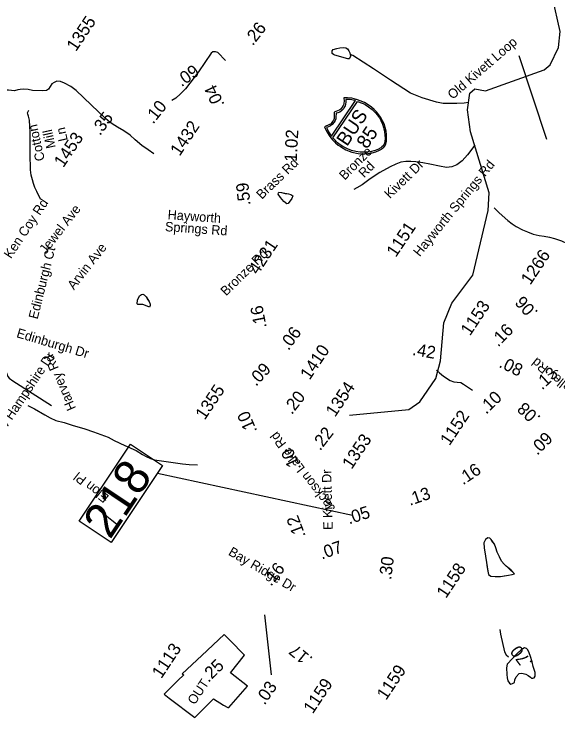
# Model space of a CAD drawing. Extents: x 1716282 to 1717158, y 799307 to 801078.
# Drawn here: x 1716897.5 to 1716976.7, y 800924.3 to 801026.4 of the extents above; entities that cross this region are included whole.
import ezdxf

# ---------------------------------------------------------------- set-up
doc = ezdxf.new("R2010")
doc.units = 0
for name, color, linetype in [('Exist Boundary Political City Limit New Hole', 7, 'Continuous'), ('Exist Hydrographic Misc Water Feature', 7, 'Continuous'), ('Exist Hydrographic Pond Under 1500 Sq Ft', 7, 'Continuous'), ('Exist Road Non-System Type 51', 7, 'Continuous'), ('Exist Road Non-System Type 51 Label', 7, 'Continuous'), ('Exist Road Primary Interstate Mileage Hundredths English Label', 7, 'Continuous'), ('Exist Road Primary Interstate Shield CELL', 7, 'Continuous'), ('Exist Road Primary Interstate Shield Number Label', 7, 'Continuous'), ('Exist Road Secondary Mileage Hundredths English Label', 7, 'Continuous'), ('Exist Road Secondary Mileage Tenths English Label', 7, 'Continuous'), ('Exist Road Secondary Structure Standard Bridge Number Label', 7, 'Continuous'), ('Exist Road Secondary Type 51 Label', 7, 'Continuous'), ('Exist Road Secondary Type 51 Number Label', 7, 'Continuous')]:
    doc.layers.add(name, color=color, linetype=linetype)

msp = doc.modelspace()

# ---------------------------------------------------------------- linework, layer by layer
at = {"layer": 'Exist Boundary Political City Limit New Hole'}
msp.add_lwpolyline([(1716926.55, 800926.63), (1716927.99, 800925.74), (1716928.64, 800925.36), (1716928.77, 800925.4), (1716931.48, 800928.47), (1716929, 800930.44), (1716931.03, 800932.98), (1716928.93, 800935.19), (1716928.1, 800935.99), (1716924.84, 800932.96), (1716921.98, 800930.29), (1716922.19, 800930.12), (1716921.36, 800929.31), (1716919.35, 800927.34), (1716920.08, 800926.73), (1716923.81, 800923.9), (1716926.55, 800926.63)], dxfattribs=at)
at = {"layer": 'Exist Hydrographic Misc Water Feature'}
for points in [[(1716946.34, 800967.98), (1716954.98, 800968.81), (1716956.62, 800969.9), (1716958.93, 800973.29), (1716959.64, 800975.89), (1716960.09, 800981.43), (1716961.27, 800984.28), (1716964.34, 800988.34), (1716966.58, 800997.77), (1716966.69, 801000.34), (1716963.97, 801009.23), (1716963.54, 801012.44), (1716963.89, 801014.85), (1716964.64, 801015.5), (1716966.16, 801015.19), (1716974.71, 801018.28), (1716975.61, 801018.99), (1716976.81, 801021.53), (1716977.04, 801023.86), (1716975.95, 801028.85), (1716977.09, 801034.23), (1716978.2, 801037.01)], [(1716963.69, 801013.49), (1716963.08, 801013.43), (1716961.99, 801013.37), (1716960.95, 801013.34), (1716960.01, 801013.35), (1716959.03, 801013.56), (1716956.97, 801014.2), (1716956.2, 801014.47), (1716955.24, 801014.85), (1716952.35, 801016.75), (1716949.85, 801018.39), (1716946.86, 801020.33), (1716946.45, 801020.5)], [(1716917.84, 801006.04), (1716917.01, 801006.61), (1716916.11, 801007.25), (1716915.12, 801008.07), (1716914.39, 801008.75), (1716913.48, 801009.37), (1716912.55, 801009.9), (1716912.14, 801010.14), (1716911.5, 801010.58), (1716910.78, 801011.18), (1716908.72, 801013.15), (1716906.53, 801015.24), (1716905.72, 801015.86), (1716904.84, 801016.32), (1716904.22, 801016.54), (1716903.71, 801016.61), (1716903.3, 801016.43), (1716902.99, 801016.22), (1716902.5, 801015.46), (1716902.19, 801015.26), (1716901.65, 801015.2), (1716900.16, 801015.27), (1716899.52, 801015.42), (1716898.79, 801015.43), (1716898.34, 801015.39), (1716898.03, 801015.35), (1716897.52, 801015.21)], [(1716897.52, 801015.21), (1716896.64, 801015.32), (1716895.85, 801015.3), (1716894.14, 801014.75), (1716893.02, 801014.28), (1716892.11, 801013.88), (1716891.63, 801013.65)], [(1716964.63, 801007.31), (1716963.56, 801005.9), (1716962.78, 801005.02), (1716962, 801004.44), (1716961.29, 801004.11), (1716960.5, 801004.05), (1716959.45, 801004.21), (1716958.04, 801004.51), (1716957.06, 801004.72), (1716956.01, 801004.87), (1716955.29, 801004.91), (1716954.58, 801004.9), (1716953.83, 801004.82), (1716953.13, 801004.52), (1716952.29, 801004.11), (1716950.77, 801003.32), (1716949.8, 801002.68), (1716949.18, 801002.23), (1716948.19, 801001.5), (1716947.44, 801001.07), (1716946.98, 801000.82)], [(1716938.09, 800999.93), (1716937.96, 800999.53), (1716937.65, 800999.14), (1716937.43, 800998.81), (1716937.23, 800998.73), (1716936.78, 800999.1), (1716936.28, 800999.66), (1716935.96, 801000.16), (1716936.01, 801000.34), (1716936.08, 801000.43), (1716936.46, 801000.38), (1716936.99, 801000.23), (1716937.46, 801000.19), (1716937.83, 801000.11), (1716938.09, 800999.93)], [(1716938.09, 800999.93), (1716937.96, 800999.53), (1716937.43, 800998.81), (1716937.23, 800998.73), (1716936.78, 800999.1), (1716936.28, 800999.66), (1716935.96, 801000.16), (1716936.01, 801000.34), (1716936.08, 801000.43), (1716936.46, 801000.38), (1716937.46, 801000.19), (1716937.83, 801000.11), (1716938.09, 800999.93)], [(1716967.46, 800998.14), (1716968.18, 800997.44), (1716969.41, 800996.31), (1716970.04, 800995.85), (1716970.64, 800995.44), (1716971.58, 800994.97), (1716972.31, 800994.65), (1716973.11, 800994.32), (1716974, 800994.13), (1716974.74, 800994.04), (1716975.48, 800993.89), (1716976.25, 800993.68), (1716977.27, 800993.37), (1716978.1, 800992.98), (1716978.92, 800992.49), (1716980.01, 800991.78), (1716980.67, 800991.3), (1716981.58, 800990.53), (1716984, 800988.11), (1716984.85, 800987.24)], [(1716917.2, 800983.71), (1716916.64, 800983.92), (1716916.22, 800984.07), (1716915.76, 800984.06), (1716915.53, 800984.08), (1716915.42, 800984.19), (1716915.45, 800984.69), (1716915.73, 800985.35), (1716916.03, 800985.53), (1716916.23, 800985.57), (1716916.45, 800985.49), (1716916.7, 800985.18), (1716916.98, 800984.77), (1716917.18, 800984.5), (1716917.29, 800984.14), (1716917.29, 800983.94), (1716917.2, 800983.71)], [(1716917.2, 800983.71), (1716916.64, 800983.92), (1716916.22, 800984.07), (1716915.76, 800984.06), (1716915.53, 800984.08), (1716915.42, 800984.19), (1716915.45, 800984.69), (1716915.73, 800985.35), (1716916.03, 800985.53), (1716916.23, 800985.57), (1716916.45, 800985.49), (1716916.7, 800985.18), (1716917.18, 800984.5), (1716917.29, 800984.14), (1716917.29, 800983.94), (1716917.2, 800983.71)], [(1716959.03, 800974.53), (1716959.48, 800974.12), (1716960.05, 800973.66), (1716961.02, 800973.03), (1716961.58, 800972.82), (1716962.05, 800972.78), (1716962.56, 800972.71), (1716962.98, 800972.5), (1716963.27, 800972.26), (1716964.27, 800971.62)], [(1716899.47, 800969.37), (1716900.44, 800968.89), (1716901.94, 800968), (1716902.71, 800967.58), (1716903.57, 800967.2), (1716904.79, 800966.87), (1716905.96, 800966.52), (1716907.77, 800965.99), (1716909.07, 800965.52), (1716911.17, 800964.75), (1716912.08, 800964.27), (1716913.59, 800963.56), (1716915.28, 800962.79), (1716916.21, 800962.25), (1716916.73, 800961.94), (1716917.33, 800961.63), (1716917.93, 800961.47), (1716922.03, 800960.89), (1716923.01, 800960.78), (1716924.18, 800960.75)], [(1716970.42, 800944.87), (1716969.91, 800945.36), (1716969.36, 800945.84), (1716968.88, 800946.27), (1716968.53, 800946.68), (1716968.2, 800947.33), (1716967.89, 800948), (1716967.68, 800948.63), (1716967.48, 800949.15), (1716967.12, 800949.65), (1716966.99, 800949.84), (1716966.83, 800950.05), (1716966.51, 800950.1), (1716966.2, 800949.85), (1716965.94, 800949.37), (1716965.99, 800948.63), (1716966.18, 800947.41), (1716966.31, 800946.51), (1716966.43, 800945.77), (1716966.5, 800945.26), (1716966.58, 800944.96), (1716966.62, 800944.76), (1716966.94, 800944.5), (1716967.59, 800944.44), (1716968.38, 800944.46), (1716968.91, 800944.56), (1716969.54, 800944.66), (1716970.04, 800944.77), (1716970.42, 800944.87)], [(1716970.42, 800944.87), (1716968.88, 800946.27), (1716968.53, 800946.68), (1716968.2, 800947.33), (1716967.89, 800948), (1716967.68, 800948.63), (1716967.48, 800949.15), (1716966.99, 800949.84), (1716966.83, 800950.05), (1716966.51, 800950.1), (1716966.2, 800949.85), (1716965.94, 800949.37), (1716965.99, 800948.63), (1716966.31, 800946.51), (1716966.5, 800945.26), (1716966.62, 800944.76), (1716966.94, 800944.5), (1716967.59, 800944.44), (1716968.38, 800944.46), (1716969.54, 800944.66), (1716970.04, 800944.77), (1716970.42, 800944.87)], [(1716968.25, 800936.76), (1716968.38, 800936.07), (1716968.94, 800933.51), (1716969.17, 800933.07), (1716969.51, 800932.74)]]:
    msp.add_lwpolyline(points, dxfattribs=at)
at = {"layer": 'Exist Hydrographic Pond Under 1500 Sq Ft'}
for points in [[(1716946.45, 801020.5), (1716946.49, 801020.26), (1716946.37, 801019.92), (1716946.31, 801019.89), (1716946.13, 801019.88), (1716944.21, 801020.42), (1716944.01, 801020.48), (1716943.81, 801020.65), (1716943.81, 801020.8), (1716943.82, 801021.03), (1716943.98, 801021.21), (1716944.51, 801021.37), (1716944.96, 801021.45), (1716945.45, 801021.5), (1716945.81, 801021.47), (1716946.05, 801021.3), (1716946.27, 801021.01), (1716946.4, 801020.74), (1716946.45, 801020.5)], [(1716970.13, 800932.54), (1716969.33, 800931.7), (1716969.24, 800931.14), (1716969.27, 800930.2), (1716969.35, 800929.68), (1716969.41, 800929.24), (1716969.66, 800928.93), (1716969.86, 800928.78), (1716970.13, 800928.86), (1716970.39, 800929.01), (1716970.44, 800929.41), (1716970.63, 800929.86), (1716971.07, 800930.32), (1716971.45, 800930.36), (1716972.03, 800930.21), (1716972.4, 800930.03), (1716972.72, 800929.78), (1716972.87, 800929.65), (1716973.07, 800929.63), (1716973.27, 800929.71), (1716973.39, 800929.93), (1716973.41, 800930.49), (1716973.14, 800931.34), (1716972.97, 800932.05), (1716972.75, 800932.82), (1716972.55, 800933.36), (1716972.35, 800933.79), (1716972.13, 800933.99), (1716971.85, 800934.07), (1716971.36, 800933.78), (1716970.8, 800933.26), (1716970.13, 800932.54)]]:
    msp.add_lwpolyline(points, dxfattribs=at)
at = {"layer": 'Exist Road Non-System Type 51'}
for p, q in [((1716971.02, 801020.36), (1716975.09, 801008.18)), ((1716909.82, 800954.18), (1716910, 800954.03)), ((1716910, 800954.03), (1716911.7, 800952.67)), ((1716911.7, 800952.67), (1716912.39, 800952.12))]:
    msp.add_line(p, q, dxfattribs=at)
for points in [[(1716928.28, 801019.64), (1716927.16, 801020.77), (1716926.82, 801020.9), (1716926.42, 801020.88), (1716926.2, 801020.69), (1716924.33, 801017.97), (1716922.46, 801015.48), (1716921.74, 801014.76), (1716921.03, 801014.13), (1716920.44, 801013.81)], [(1716901.39, 800999.37), (1716901.13, 800999.81), (1716900.78, 801000.52), (1716900.5, 801001.13), (1716900.3, 801001.69), (1716900.16, 801002.23), (1716899.97, 801002.94), (1716899.88, 801003.68), (1716899.85, 801004.46), (1716899.82, 801005.24), (1716899.8, 801006.02), (1716899.82, 801006.87), (1716899.83, 801007.73), (1716899.83, 801008.5), (1716899.81, 801009.22), (1716899.78, 801010.01), (1716899.71, 801010.91), (1716899.58, 801011.51), (1716899.46, 801011.82), (1716899.44, 801012.02), (1716899.6, 801012.38)], [(1716895.93, 800975.26), (1716896.58, 800973.57), (1716896.77, 800973.35), (1716897.31, 800972.94), (1716902.94, 800969.36)], [(1716912.39, 800952.12), (1716912.46, 800952.07)]]:
    msp.add_lwpolyline(points, dxfattribs=at)
at = {"layer": 'Exist Road Primary Interstate Shield CELL'}
for points in [[(1716951.5, 801007.16), (1716951.56, 801007.28), (1716951.64, 801007.45), (1716951.69, 801007.64), (1716951.73, 801007.86), (1716951.75, 801008.2), (1716951.77, 801008.48), (1716951.77, 801008.82), (1716951.7, 801009.33), (1716951.57, 801009.86), (1716951.39, 801010.39), (1716951.18, 801010.84), (1716950.91, 801011.3), (1716950.65, 801011.71), (1716950.31, 801012.13), (1716949.95, 801012.49), (1716949.55, 801012.82), (1716949.1, 801013.17), (1716948.54, 801013.5), (1716947.93, 801013.77), (1716947.53, 801013.91), (1716947.03, 801014.05), (1716946.69, 801014.12), (1716946.06, 801014.18), (1716945.55, 801014.19), (1716945.57, 801013.71), (1716945.54, 801013.42), (1716945.51, 801013.25), (1716945.44, 801013.09), (1716945.31, 801012.83), (1716945.2, 801012.68), (1716945.07, 801012.55), (1716944.96, 801012.45), (1716944.85, 801012.38), (1716944.14, 801012.08), (1716944.13, 801011.32), (1716944.11, 801011.17), (1716944.06, 801011.04), (1716944.01, 801010.91), (1716943.9, 801010.72), (1716943.8, 801010.58), (1716943.68, 801010.46), (1716943.58, 801010.36), (1716943.43, 801010.28), (1716942.73, 801009.96), (1716942.89, 801009.54), (1716943.08, 801009.16), (1716943.39, 801008.69), (1716943.65, 801008.35), (1716943.87, 801008.08), (1716944.31, 801007.64), (1716944.71, 801007.3), (1716945.02, 801007.08), (1716945.84, 801006.62), (1716946.31, 801006.42), (1716946.7, 801006.29), (1716947.62, 801006.09), (1716948.17, 801006.03), (1716948.58, 801006.03), (1716949.08, 801006.07), (1716949.33, 801006.1), (1716950.17, 801006.33), (1716950.65, 801006.52), (1716951, 801006.71), (1716951.14, 801006.81), (1716951.34, 801006.98)], [(1716943.02, 801009.86), (1716943.13, 801009.59), (1716943.31, 801009.25), (1716943.51, 801008.94), (1716943.74, 801008.61), (1716947.23, 801013.8), (1716946.87, 801013.86), (1716946.52, 801013.92), (1716946.18, 801013.95), (1716945.83, 801013.94), (1716945.82, 801013.53), (1716945.77, 801013.25), (1716945.72, 801013.04), (1716945.65, 801012.87), (1716945.52, 801012.64), (1716945.45, 801012.54), (1716945.17, 801012.27), (1716944.94, 801012.12), (1716944.67, 801012.01), (1716944.41, 801011.95), (1716944.38, 801011.37), (1716944.34, 801011.13), (1716944.25, 801010.89), (1716944.13, 801010.64), (1716943.85, 801010.31), (1716943.57, 801010.1), (1716943.29, 801009.94)], [(1716947.5, 801013.66), (1716947.69, 801013.62), (1716948.06, 801013.48), (1716948.34, 801013.35), (1716948.66, 801013.2), (1716949.14, 801012.85), (1716949.64, 801012.49), (1716949.91, 801012.24), (1716950.15, 801011.99), (1716950.4, 801011.7), (1716950.71, 801011.28), (1716950.93, 801010.86), (1716951.15, 801010.37), (1716951.31, 801009.88), (1716951.38, 801009.68), (1716951.46, 801009.31), (1716951.51, 801008.72), (1716951.53, 801008.29), (1716951.51, 801007.82), (1716951.47, 801007.59), (1716951.38, 801007.36), (1716951.25, 801007.21), (1716951.07, 801007.04), (1716950.91, 801006.91), (1716950.49, 801006.68), (1716950.1, 801006.52), (1716949.39, 801006.31), (1716948.91, 801006.25), (1716948.4, 801006.25), (1716947.89, 801006.27), (1716947.26, 801006.36), (1716946.67, 801006.52), (1716946.07, 801006.75), (1716945.38, 801007.1), (1716944.99, 801007.35), (1716944.63, 801007.62), (1716944.46, 801007.79), (1716944.25, 801008), (1716943.94, 801008.34)]]:
    msp.add_lwpolyline(points, close=True, dxfattribs=at)
at = {"layer": 'Exist Road Secondary Mileage Tenths English Label'}
msp.add_line((1716933.97, 800938.9), (1716934.96, 800930.12), dxfattribs=at)
at = {"layer": 'Exist Road Secondary Structure Standard Bridge Number Label'}
msp.add_line((1716946.81, 800953.34), (1716918.39, 800959.44), dxfattribs=at)
msp.add_lwpolyline([(1716906.97, 800952.53), (1716914.46, 800963.72), (1716919.09, 800960.62), (1716911.6, 800949.43)], close=True, dxfattribs=at)

# ---------------------------------------------------------------- texts
at = {"layer": 'Exist Boundary Political City Limit New Hole'}
msp.add_text('OUT', height=1.377, rotation=56.2051, dxfattribs=at).set_placement((1716923.79, 800925.68))
at = {"layer": 'Exist Road Non-System Type 51 Label'}
for s, rotation, p in [('Hayworth Springs Rd', 50.6744, (1716956.58, 800990.96)), ('Edinburgh Ct', 75.8693, (1716900.89, 800981.86)), ('Edinburgh Dr', 343.2985, (1716897.73, 800979.34)), ('New Hampshire Dr', 56.2051, (1716894.81, 800963.65)), ('E Kivett Dr', 91.5309, (1716943.92, 800951.26)), ('Bay Ridge Dr', 329.7793, (1716928.59, 800947.67))]:
    msp.add_text(s, height=1.3775, rotation=rotation, dxfattribs=at).set_placement(p)
at = {"layer": 'Exist Road Primary Interstate Mileage Hundredths English Label'}
for s, height, rotation, p in [('1.02', 1.812, 86.924, (1716938.66, 801004.82)), ('.30', 1.813, 82.9551, (1716952.43, 800943.91))]:
    msp.add_text(s, height=height, rotation=rotation, dxfattribs=at).set_placement(p)
at = {"layer": 'Exist Road Primary Interstate Shield Number Label'}
for s, p in [('BUS', (1716946, 801007.01)), ('85', (1716948.91, 801006.62))]:
    msp.add_text(s, height=2.03, rotation=56.2051, dxfattribs=at).set_placement(p)
at = {"layer": 'Exist Road Secondary Mileage Hundredths English Label'}
for s, height, rotation, p in [('.26', 1.812, 52.0562, (1716932.26, 801021.67)), ('.04', 1.812, 114.6529, (1716928.18, 801013.21)), ('.59', 1.812, 96.106, (1716931.95, 800998.57)), ('.16', 1.812, 45.55, (1716968.02, 800977.81)), ('.08', 1.812, 334.1626, (1716968.01, 800975.01)), ('.10', 1.812, 43.8307, (1716966.28, 800968.02)), ('.08', 1.812, 136.4002, (1716974.31, 800967.67)), ('.10', 1.812, 114.0833, (1716932.94, 800965.67)), ('.09', 1.813, 44.5626, (1716973.72, 800962.02)), ('.16', 1.812, 33.7889, (1716962.9, 800957.72)), ('.13', 1.812, 19.132, (1716955.15, 800954.74)), ('.05', 1.812, 18.038, (1716946.31, 800952.04)), ('.12', 1.812, 110.8303, (1716940, 800950.38)), ('.07', 1.812, 19.1626, (1716942.32, 800946.92)), ('.16', 1.812, 50.6405, (1716934.91, 800942.95)), ('.17', 1.812, 140.9664, (1716941.12, 800932.59)), ('.25', 1.813, 44.3039, (1716925.8, 800928.95)), ('.03', 1.812, 55.421, (1716933.98, 800925.64))]:
    msp.add_text(s, height=height, rotation=rotation, dxfattribs=at).set_placement(p)
at = {"layer": 'Exist Road Secondary Mileage Tenths English Label'}
for s, height, rotation, p in [('.09', 1.812, 35.3635, (1716921.88, 801015.72)), ('.10', 1.812, 51.5549, (1716917.74, 801010.27)), ('.35', 1.812, 52.7263, (1716909.99, 801008.58)), ('.06', 1.813, 132.0786, (1716973.93, 800982.99)), ('.16', 1.812, 101.1906, (1716934.3, 800980.76)), ('.06', 1.813, 54.1756, (1716937.47, 800977.28)), ('.42', 1.812, 349.8826, (1716955.43, 800976.74)), ('.09', 1.812, 47.3024, (1716932.75, 800972.07)), ('.13', 1.812, 42.8464, (1716974.42, 800971.55)), ('.20', 1.812, 51.7607, (1716937.95, 800967.95)), ('.22', 1.812, 52.2625, (1716942.08, 800962.68)), ('.10', 1.812, 114.3782, (1716939.35, 800960.24)), ('.70', 1.813, 126.9899, (1716973.11, 800931.91))]:
    msp.add_text(s, height=height, rotation=rotation, dxfattribs=at).set_placement(p)
at = {"layer": 'Exist Road Secondary Structure Standard Bridge Number Label'}
msp.add_text('218', height=5.075, rotation=56.2051, dxfattribs=at).set_placement((1716911.46, 800949.74))
at = {"layer": 'Exist Road Secondary Type 51 Label'}
for s, height, rotation, p in [('Old Kivett Loop', 1.3775, 40.8106, (1716961.38, 801013.88)), ('Cotton', 1.377, 102.4636, (1716901.97, 801005.13)), (' Mill', 1.377, 102.4636, (1716903.66, 801006.48)), (' Ln', 1.377, 102.4636, (1716905.42, 801007.5)), ('Bronze', 1.377, 45.1286, (1716945.65, 801002.11)), ('Brass Rd', 1.377, 43.8827, (1716933.57, 800999.32)), (' Rd', 1.377, 45.1286, (1716948.11, 801002.08)), ('Kivett Dr', 1.377, 44.3608, (1716952.25, 800999.41)), ('Ken Coy Rd', 1.377, 56.2051, (1716897.01, 800990.67)), ('Jewel Ave', 1.377, 52.045, (1716902.1, 800991.34)), ('Hayworth ', 1.377, 355.9665, (1716919.82, 800996.51)), ('Springs Rd', 1.377, 355.9665, (1716919.43, 800994.77)), ('Arvin Ave', 1.377, 52.0685, (1716906.2, 800986.13)), ('Bronze Rd', 1.377, 44.4168, (1716928.37, 800985.25)), ('Harvey Rd', 1.377, 113.3438, (1716906.53, 800968.98)), ('Kersey Valley Rd', 1.3775, 141.2373, (1716984.63, 800967.6)), ('Jackson Lake Rd', 1.3775, 127.3193, (1716944.35, 800954.46)), ('Elon Pl', 1.377, 141.4566, (1716911.42, 800956.15))]:
    msp.add_text(s, height=height, rotation=rotation, dxfattribs=at).set_placement(p)
at = {"layer": 'Exist Road Secondary Type 51 Number Label'}
for s, p in [('1355', (1716906.49, 801020.83)), ('1432', (1716921.6, 801005.59)), ('1453', (1716904.65, 801003.92)), ('1151', (1716953.11, 800990.86)), ('4231', (1716933, 800988.31)), ('1266', (1716972.7, 800986.82)), ('1153', (1716963.92, 800979.42)), ('1410', (1716940.54, 800972.98)), ('1354', (1716944.25, 800967.58)), ('1355', (1716925.26, 800967.16)), ('1152', (1716960.92, 800963.41)), ('1353', (1716946.66, 800959.97)), ('1158', (1716960.41, 800941.17)), ('1113', (1716918.93, 800929.49)), ('1159', (1716951.69, 800926.34)), ('1159', (1716941, 800924.36))]:
    msp.add_text(s, height=1.812, rotation=56.2051, dxfattribs=at).set_placement(p)

doc.saveas('drawing.dxf')
